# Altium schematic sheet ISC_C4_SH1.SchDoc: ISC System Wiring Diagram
size B; DrawnBy: Filiberto Clara; Engineer: Filiberto Clara; Organization: LIGO Laboratory; Address1: California Institute of Technology; Address2: Massachusetts Institute of Technology; SheetNumber: 8; SheetTotal: 37
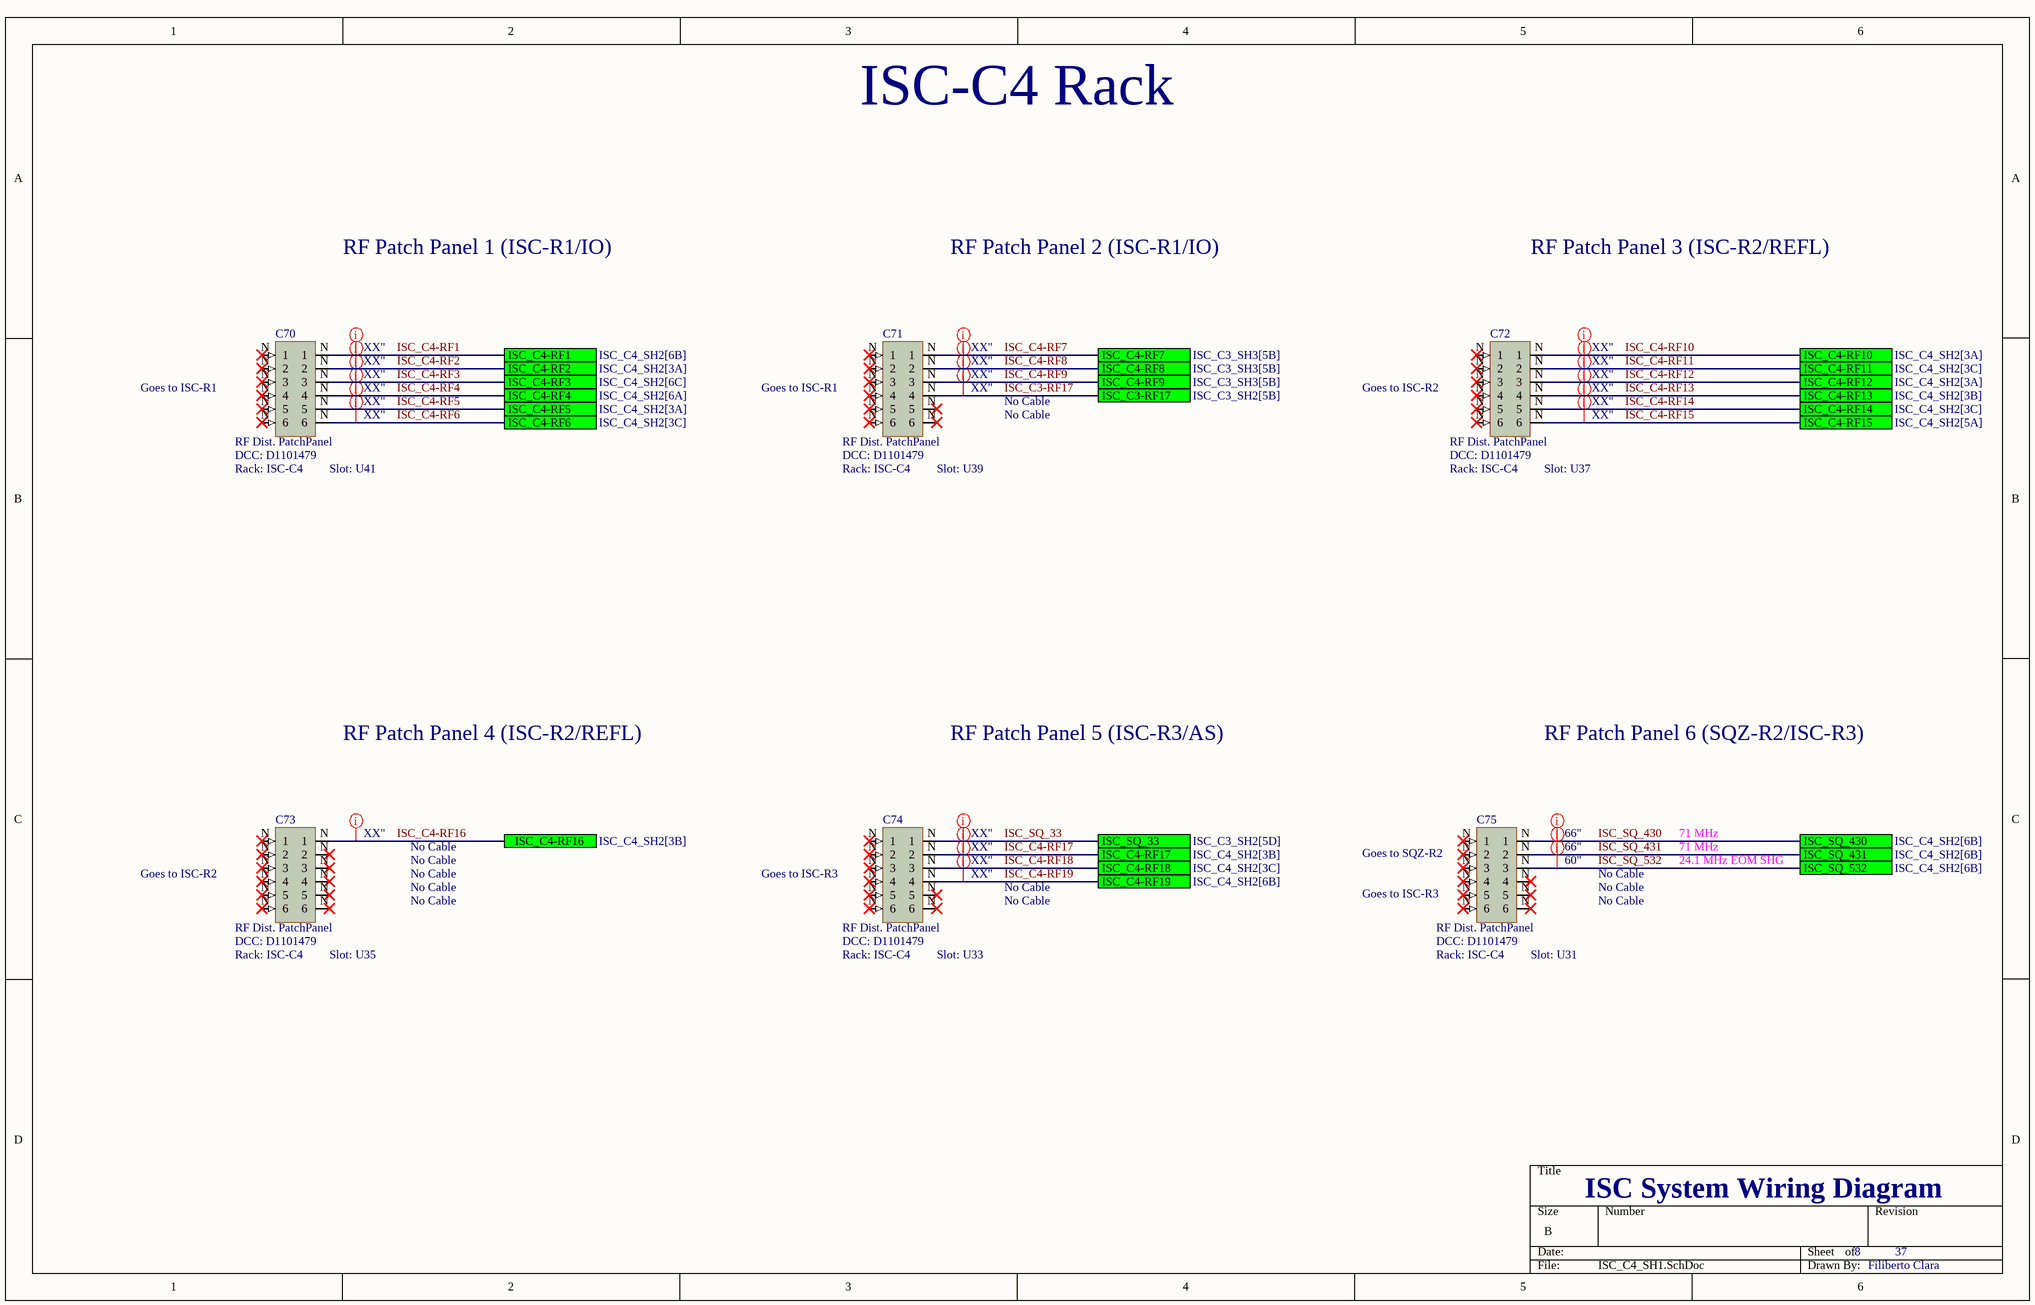
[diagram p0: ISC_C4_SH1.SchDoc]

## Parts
C70  RF Dist. PatchPanel  DCC: D1101479  Rack: ISC-C4  Slot: U41
C71  RF Dist. PatchPanel  DCC: D1101479  Rack: ISC-C4  Slot: U39
C72  RF Dist. PatchPanel  DCC: D1101479  Rack: ISC-C4  Slot: U37
C73  RF Dist. PatchPanel  DCC: D1101479  Rack: ISC-C4  Slot: U35
C74  RF Dist. PatchPanel  DCC: D1101479  Rack: ISC-C4  Slot: U33
C75  RF Dist. PatchPanel  DCC: D1101479  Rack: ISC-C4  Slot: U31

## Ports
ISC_C3-RF17 (see ISC_C3_SH2[5B]), ISC_C4-RF1 (see ISC_C4_SH2[6B]), ISC_C4-RF2 (see ISC_C4_SH2[3A]), ISC_C4-RF3 (see ISC_C4_SH2[6C]), ISC_C4-RF4 (see ISC_C4_SH2[6A]), ISC_C4-RF5 (see ISC_C4_SH2[3A]), ISC_C4-RF6 (see ISC_C4_SH2[3C]), ISC_C4-RF7 (see ISC_C3_SH3[5B]), ISC_C4-RF8 (see ISC_C3_SH3[5B]), ISC_C4-RF9 (see ISC_C3_SH3[5B]), ISC_C4-RF10 (see ISC_C4_SH2[3A]), ISC_C4-RF11 (see ISC_C4_SH2[3C]), ISC_C4-RF12 (see ISC_C4_SH2[3A]), ISC_C4-RF13 (see ISC_C4_SH2[3B]), ISC_C4-RF14 (see ISC_C4_SH2[3C]), ISC_C4-RF15 (see ISC_C4_SH2[5A]), ISC_C4-RF16 (see ISC_C4_SH2[3B]), ISC_C4-RF17 (see ISC_C4_SH2[3B]), ISC_C4-RF18 (see ISC_C4_SH2[3C]), ISC_C4-RF19 (see ISC_C4_SH2[6B]), ISC_SQ_33 (see ISC_C3_SH2[5D]), ISC_SQ_430 (see ISC_C4_SH2[6B]), ISC_SQ_431 (see ISC_C4_SH2[6B]), ISC_SQ_532 (see ISC_C4_SH2[6B])

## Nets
ISC_C3-RF17: C71.N(4) ; port ISC_C3-RF17
ISC_C4-RF1: C70.N(1) ; port ISC_C4-RF1
ISC_C4-RF2: C70.N(2) ; port ISC_C4-RF2
ISC_C4-RF3: C70.N(3) ; port ISC_C4-RF3
ISC_C4-RF4: C70.N(4) ; port ISC_C4-RF4
ISC_C4-RF5: C70.N(5) ; port ISC_C4-RF5
ISC_C4-RF6: C70.N(6) ; port ISC_C4-RF6
ISC_C4-RF7: C71.N(1) ; port ISC_C4-RF7
ISC_C4-RF8: C71.N(2) ; port ISC_C4-RF8
ISC_C4-RF9: C71.N(3) ; port ISC_C4-RF9
ISC_C4-RF10: C72.N(1) ; port ISC_C4-RF10
ISC_C4-RF11: C72.N(2) ; port ISC_C4-RF11
ISC_C4-RF12: C72.N(3) ; port ISC_C4-RF12
ISC_C4-RF13: C72.N(4) ; port ISC_C4-RF13
ISC_C4-RF14: C72.N(5) ; port ISC_C4-RF14
ISC_C4-RF15: C72.N(6) ; port ISC_C4-RF15
ISC_C4-RF16: C73.N(1) ; port ISC_C4-RF16
ISC_C4-RF17: C74.N(2) ; port ISC_C4-RF17
ISC_C4-RF18: C74.N(3) ; port ISC_C4-RF18
ISC_C4-RF19: C74.N(4) ; port ISC_C4-RF19
ISC_SQ_33: C74.N(1) ; port ISC_SQ_33
ISC_SQ_430: C75.N(1) ; port ISC_SQ_430
ISC_SQ_431: C75.N(2) ; port ISC_SQ_431
ISC_SQ_532: C75.N(3) ; port ISC_SQ_532

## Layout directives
Length: XX": ISC_C3-RF17, ISC_C4-RF1, ISC_C4-RF2, ISC_C4-RF3, ISC_C4-RF4, ISC_C4-RF5, ISC_C4-RF6, ISC_C4-RF7, ISC_C4-RF8, ISC_C4-RF9, ISC_C4-RF10, ISC_C4-RF11, ISC_C4-RF12, ISC_C4-RF13, ISC_C4-RF14, ISC_C4-RF15, ISC_C4-RF16, ISC_C4-RF17, ISC_C4-RF18, ISC_C4-RF19, ISC_SQ_33
Length: 66": ISC_SQ_430, ISC_SQ_431
Length: 60": ISC_SQ_532

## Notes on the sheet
- ISC-C4 Rack
- RF Patch Panel 1 (ISC-R1/IO)
- RF Patch Panel 2 (ISC-R1/IO)
- RF Patch Panel 3 (ISC-R2/REFL)
- (near C70) Goes to ISC-R1
- (near C71) Goes to ISC-R1
- No Cable
- (near C72) Goes to ISC-R2
- RF Patch Panel 4 (ISC-R2/REFL)
- RF Patch Panel 5 (ISC-R3/AS)
- RF Patch Panel 6 (SQZ-R2/ISC-R3)
- 71 MHz
- (near C73) Goes to ISC-R2
- (near C74) Goes to ISC-R3
- (near C75) Goes to SQZ-R2
- (near C75) Goes to ISC-R3
- 24.1 MHz EOM SHG

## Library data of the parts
C70-C75 = RF Dist. PatchPanel: Serial: Sxxxxxxx; System: ISC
